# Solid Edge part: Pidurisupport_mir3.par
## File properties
Author: Türk
Template: Iso Part.par
Last saved by: Türk
Revision: 2
Application: Solid Edge
Accuracy: 0,990
Username: Türk
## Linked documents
Pidurisupport.par
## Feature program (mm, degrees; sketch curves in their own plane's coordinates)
part copy "CopiedPart_1"
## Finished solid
Body 1: solid body, 64 faces, 125 edges, 62 vertices.
  Faces by surface: plane 27, cylinder 22, cone 13, spline 2
  Edges by curve: circle 63, line 40, intersection 10, ellipse 8, curve on surface 4
Bounding box of the edges (mm; curved faces can reach further): 96.748 x 152.000 x 85.456, from (-27.7472, -70, -26.5) to (69.0008, 82, 58.9555).
Cylindrical faces by radius (mm): R4 x8, R5 x2, R10 x6, R12.5 x3, R60 x2, R100 x1
Conical faces (half-angle, radius in mm at the cone's reference point): 45 deg R5 x2, 45 deg R12.5 x6, 45 deg R60 x1, 45 deg R61 x2, 45 deg R99 x1, 45 deg R100 x1
Planar faces by outward normal: +x 2, +y 8, -y 7, -z 2, oblique 8
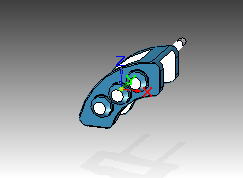
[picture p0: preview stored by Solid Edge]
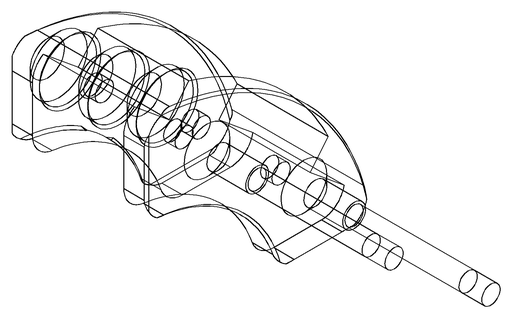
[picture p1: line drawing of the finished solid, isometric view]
